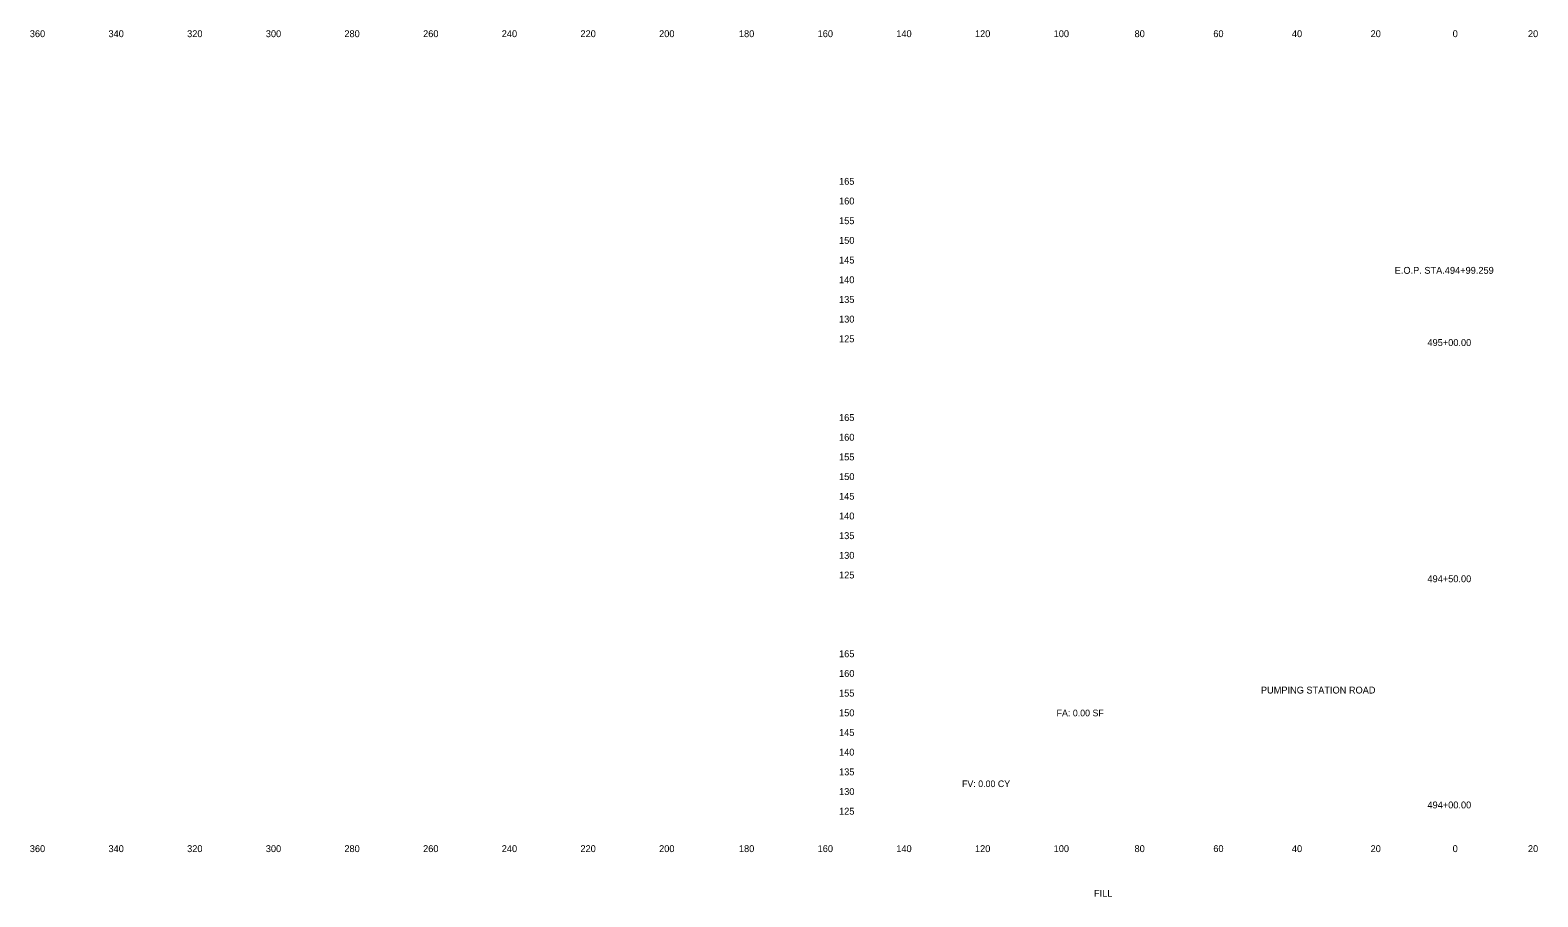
# Model space of a CAD drawing. Extents: x 21281 to 22024, y 6472 to 6918.
# Drawn here: x 21280.5 to 21663.8, y 6694 to 6914.1 of the extents above; entities that cross this region are included whole.
import ezdxf

# ---------------------------------------------------------------- set-up
doc = ezdxf.new("R2010")
doc.units = 0
for name, color, linetype in [('XS_SHEET_EW_TX_AREA', 7, 'Continuous'), ('XS_SHEET_EW_TX_VOLUME', 7, 'Continuous'), ('XS_SHEET_LABELS_OFFSET', 7, 'Continuous')]:
    doc.layers.add(name, color=color, linetype=linetype)

msp = doc.modelspace()

# ---------------------------------------------------------------- texts
at = {"layer": 'XS_SHEET_EW_TX_AREA'}
msp.add_text('FA: 0.00 SF', height=1.68, dxfattribs=at).set_placement((21541.44, 6739.84))
msp.add_text('FA: 0.00 SF', height=1.68, dxfattribs=at).set_placement((21541.44, 6739.84))
at = {"layer": 'XS_SHEET_EW_TX_VOLUME'}
for s, height, p in [('  180  ', 1.75, (21459.39, 6912.34)), ('  160  ', 1.75, (21479.4, 6912.34)), ('  140  ', 1.75, (21499.39, 6912.34)), ('  120  ', 1.75, (21519.39, 6912.34)), ('  100  ', 1.75, (21539.39, 6912.34)), ('  80  ', 1.75, (21559.95, 6912.34)), ('  60  ', 1.75, (21579.97, 6912.34)), ('  40  ', 1.75, (21599.95, 6912.34)), ('  20  ', 1.75, (21619.95, 6912.34)), ('  0  ', 1.75, (21640.81, 6912.34)), ('  0  ', 1.75, (21640.81, 6912.34)), ('  20  ', 1.75, (21659.95, 6912.34)), ('  165  ', 1.75, (21484.84, 6874.84)), ('  160  ', 1.75, (21484.84, 6869.84)), ('  155  ', 1.75, (21484.84, 6864.84)), ('  150  ', 1.75, (21484.84, 6859.84)), ('  145  ', 1.75, (21484.84, 6854.84)), ('E.O.P. STA.494+99.259', 1.75, (21627.38, 6852.23)), ('  140  ', 1.75, (21484.84, 6849.84)), ('  135  ', 1.75, (21484.84, 6844.84)), ('  130  ', 1.75, (21484.84, 6839.84)), ('  125  ', 1.75, (21484.84, 6834.84)), ('  495+00.00  ', 1.75, (21634.4, 6833.89)), ('  165  ', 1.75, (21484.84, 6814.84)), ('  160  ', 1.75, (21484.84, 6809.84)), ('  155  ', 1.75, (21484.84, 6804.84)), ('  150  ', 1.75, (21484.84, 6799.84)), ('  145  ', 1.75, (21484.84, 6794.84)), ('  140  ', 1.75, (21484.84, 6789.84)), ('  135  ', 1.75, (21484.84, 6784.84)), ('  130  ', 1.75, (21484.84, 6779.84)), ('  125  ', 1.75, (21484.84, 6774.84)), ('  494+50.00  ', 1.75, (21634.4, 6773.89)), ('  165  ', 1.75, (21484.84, 6754.84)), ('  160  ', 1.75, (21484.84, 6749.84)), ('  155  ', 1.75, (21484.84, 6744.84)), ('PUMPING STATION ROAD', 1.75, (21593.37, 6745.62)), ('  150  ', 1.75, (21484.84, 6739.84)), ('  145  ', 1.75, (21484.84, 6734.84)), ('  140  ', 1.75, (21484.84, 6729.84)), ('  135  ', 1.75, (21484.84, 6724.84)), ('FV: 0.00 CY', 1.68, (21517.39, 6721.85)), ('  130  ', 1.75, (21484.84, 6719.84)), ('  494+00.00  ', 1.75, (21634.4, 6716.44)), ('  125  ', 1.75, (21484.84, 6714.84)), ('  160  ', 1.75, (21479.4, 6705.34)), ('  140  ', 1.75, (21499.39, 6705.34)), ('  120  ', 1.75, (21519.39, 6705.34)), ('  100  ', 1.75, (21539.39, 6705.34)), ('  80  ', 1.75, (21559.95, 6705.34)), ('  60  ', 1.75, (21579.97, 6705.34)), ('  40  ', 1.75, (21599.95, 6705.34)), ('  20  ', 1.75, (21619.95, 6705.34)), ('  0  ', 1.75, (21640.81, 6705.34)), ('  0  ', 1.75, (21640.81, 6705.34)), ('  20  ', 1.75, (21659.95, 6705.34)), ('FILL', 1.75, (21550.93, 6693.98))]:
    msp.add_text(s, height=height, dxfattribs=at).set_placement(p)
at = {"layer": 'XS_SHEET_LABELS_OFFSET'}
for s, p in [('  360  ', (21279.14, 6912.34)), ('  340  ', (21299.13, 6912.34)), ('  320  ', (21319.13, 6912.34)), ('  300  ', (21339.13, 6912.34)), ('  280  ', (21359.1, 6912.34)), ('  260  ', (21379.11, 6912.34)), ('  240  ', (21399.1, 6912.34)), ('  220  ', (21419.1, 6912.34)), ('  200  ', (21439.1, 6912.34)), ('  360  ', (21279.14, 6705.34)), ('  340  ', (21299.13, 6705.34)), ('  320  ', (21319.13, 6705.34)), ('  300  ', (21339.13, 6705.34)), ('  280  ', (21359.1, 6705.34)), ('  260  ', (21379.11, 6705.34)), ('  240  ', (21399.1, 6705.34)), ('  220  ', (21419.1, 6705.34)), ('  200  ', (21439.1, 6705.34)), ('  180  ', (21459.39, 6705.34))]:
    msp.add_text(s, height=1.75, dxfattribs=at).set_placement(p)

doc.saveas('drawing.dxf')
